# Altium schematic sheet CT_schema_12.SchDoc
size 287 x 160 mm
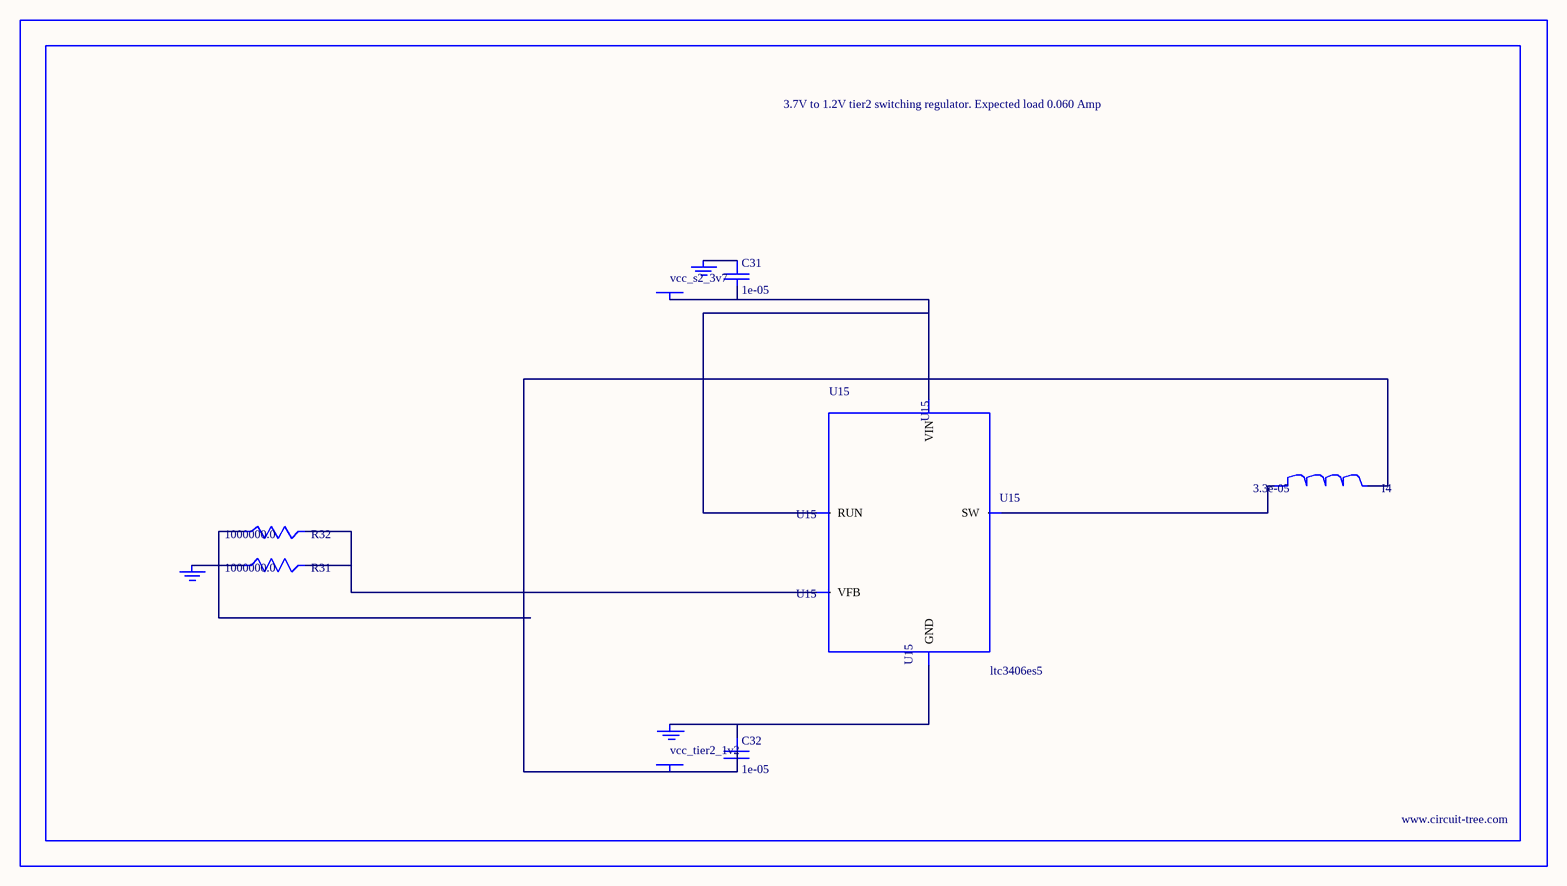
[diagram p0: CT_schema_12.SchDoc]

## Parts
BORDER11  (no value)
C31  1e-05  [C0805]
C32  1e-05  [C0805]
GND_INSTANCE_11_0  (no value)
GND_INSTANCE_11_1  (no value)
GND_INSTANCE_11_2  (no value)
I4  3.3e-05  [L1210]
POWER_INSTANCE_11_0  vcc_tier2_1v2
POWER_INSTANCE_11_1  vcc_s2_3v7
R31  1000000.0  [R0603]
R32  1000000.0  [R0603]
U15  ltc3406es5  [TSOT-23-5]

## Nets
NetC31_1: C31.1 GND_INSTANCE_11_1.0(GND)
NetC31_2: C31.2 POWER_INSTANCE_11_1.0(PWR) U15.1(RUN) U15.4(VIN)
NetC32_1: C32.1 GND_INSTANCE_11_0.0(GND) U15.2(GND)
NetC32_2: C32.2 I4.2 POWER_INSTANCE_11_0.0(PWR) R32.1
NetGND_INSTANCE_11_2_0: GND_INSTANCE_11_2.0(GND) R31.1
NetI4_1: I4.1 U15.3(SW)
NetR31_2: R31.2 R32.2 U15.5(VFB)

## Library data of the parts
BORDER11 = BORDER_PAGE11
C31 C32 = C0805C106K8RACTU
GND_INSTANCE_11_0-GND_INSTANCE_11_2 = GND
I4 = L1210R330MDWIT
POWER_INSTANCE_11_0 POWER_INSTANCE_11_1 = PWR
R31 R32 = RC0603JR-071ML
